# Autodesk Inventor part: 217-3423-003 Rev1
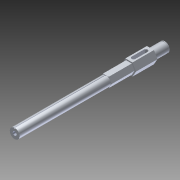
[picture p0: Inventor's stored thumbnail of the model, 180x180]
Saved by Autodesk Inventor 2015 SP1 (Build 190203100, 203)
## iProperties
Created: 2014-11
Part Number: 217-3423-003 Rev1
Material: Generic
Document SubType Name: Modeling
Designer: User
Density: 1 g/cm^3
Appearance: Default
Author: User
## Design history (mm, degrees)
node "217-3423-003 Rev1.ipt1"
sketch "Sketch1"
  geometry: L1 (4.583, 0)-(-2.75, 0) reference; L2 (0.917, 0)-(0.917, -6.35); L3 (0.123, -0.05)-(0.123, -0.794); L4 (0.123, -0.794)-(1.71, -0.794); L5 (1.71, -0.794)-(1.71, -0.05); L6 (1.833, 0)-(0, 0) reference; C1 r 10.929 at (0.917, -6.35); A1 r 6.35 centre (0.917, -6.35) between (0.123, -0.05) and (1.71, -0.05); 3 further points
  constraints: 8 end point, 3 midpoint, 2 centre point, 2 coincident, 2 perpendicular, 2 point on circle, 2 vertical, 1 point on line, 1 vertical alignment
  dimensions: "d0" = 12.7 diameter of A1; "d1" = 21.85716 diameter of C1; "d4" = 1.5875 distance of L3.end L4.end; "d5" = 0.79375 distance of L2.start point (0.917, -0.794)
extrude "Extrusion2" cut sketch "Sketch1" distance "d6" = 31.75; taper "d7" = 0 deg
node "1_4-20 Tapped Hole1"
node "Base1"
